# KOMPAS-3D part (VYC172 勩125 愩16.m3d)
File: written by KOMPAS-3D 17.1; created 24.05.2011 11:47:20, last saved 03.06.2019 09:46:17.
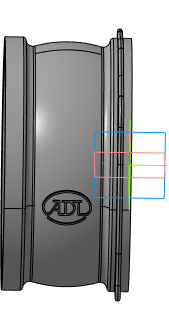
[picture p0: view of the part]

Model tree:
1. Плоскость XY
2. Плоскость ZX
3. Плоскость ZY
4. Ось X
5. Ось Y
6. Ось Z
7. Начало координат
8. Операция без истории:3
9. Операция без истории:4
